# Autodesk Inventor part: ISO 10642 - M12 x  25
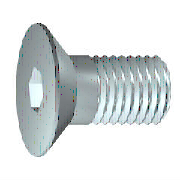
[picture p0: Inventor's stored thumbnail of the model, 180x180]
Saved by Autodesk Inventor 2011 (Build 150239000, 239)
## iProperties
Created: 2010-02
Part Number: ISO 10642 - M12 x  25
Material: Steel
Description: Hexagon Socket Countersunk Head Screw-1 - Product grade A
Document SubType Name: Modeling
Standard: ISO 10642
Designer: 129877
Standard Revision: Second edition 2004-03-01
Standards Organization: ISO
Language: en-US
Size Designation: M12 x  25
Categories: <MemberInstance><Categories><Category DisplayName="Fasteners" InternalName="e4da775c-781d-43d5-af7c-5136215cf5a6" Mnemonic="FSTN"><Category DisplayName="Bolts"
Density: 7.85 g/cm^3
Mass: 29.8359 g
Surface Area: 18.9895 cm^2
Volume: 3.80075 cm^3
IsCustomPart: 0
Author: 129877
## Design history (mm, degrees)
body "Solid1"
workplane "Work Plane1"
revolve "Body" stored, may be unused: angle "d13" = 90 deg
sketch "Sketch2"
  geometry: L1 (0, -16.184)-(0, 16.184) reference; L2 (-16.184, 0)-(16.184, 0) reference; L3 (4.619, 0)-(2.309, -4); L4 (2.309, -4)-(-2.309, -4); L5 (-2.309, -4)-(-4.619, 0); L6 (-4.619, 0)-(-2.309, 4); L7 (-2.309, 4)-(2.309, 4); L8 (2.309, 4)-(4.619, 0); A1 r 4.619 centre (0, 0) between (0, 4.619) and (4.619, 0) reference; 2 further points
  constraints: 12 end point, 2 coincident, 2 point on circle, 2 point on line, 12 other
extrude "Slot" join sketch "Sketch2" taper "d14" = 0 deg; stored distance "d30" = 10
feature "Thread" dims "d15" = 11.5 (= GEL), "d16" = 0
chamfer "Chamfer1" distance "d17" = 1.07354 (= -0.5 x SPD + 0.5 x GD); stored, may be unused: second distance "d18" = 1.07354 (= GUL), angle "d39" = 45 deg
sketch "Sketch1"
  geometry: L1 (25, 0)-(25, 6); L2 (25, 6)-(13.5, 6); L3 (13.5, 6)-(12.426, 6); L4 (0, 11.56)-(0, 4.619); L5 (0, 4.619)-(5.19, 4.619); L6 (5.19, 4.619)-(7.857, 0); L7 (7.857, 0)-(25, 0); L8 (0, 11.56)-(1.88, 11.56); L9 (1.88, 11.56)-(7.44, 6); L10 (12.426, 6)-(7.44, 6); L11 (13.5, 6)-(7.44, 6); L12 (7.44, 6)-(7.44, 6); L13 (-5, 0)-(30, 0) reference; L14 (0, -2.312)-(0, 13.872) reference
  constraints: 24 end point, 4 collinear, 3 parallel
  dimensions: "d0" = 25 distance between parallel lines of L4 L1 (= NLG); "d1" = 11.5 distance from line of L2.end L1 (= GEL); "d2" = 5.19 distance from line of L5.end L4 (= INTI); "d3" = 12 diameter of L2 L7 (= GD); "d6" = 7.44 distance from line of L9.end L4 (= KOH); "d7" = 45 deg angle of L9 L7 (= 0.5 x SEWI); "d8" = 9.2376 diameter of L5 L7 (= 1.1547 x SW); "d9" = 60 deg angle of L6 L7; "d10" = 23.12 diameter of L8 L7 (= KOD); "d11" = 12 diameter of L10 L7 (= BDM); "d12" = 1.07354 distance of L3.end L2.end (= GAL)
other parameters: "NLG" = 25 [user parameter; used in 1 equation term], "INTI" = 5.19 [user parameter; used in 1 equation term], "GEL" = 11.5 [user parameter; used in 2 equation terms], "GAL" = 1.07354 (= 0.61345 x PTC) [user parameter; used in 1 equation term], "KOH" = 7.44 [user parameter; used in 1 equation term], "KOD" = 23.12 [user parameter; used in 1 equation term], "GUL" = 1.07354 (= 0.61345 x PTC) [user parameter; used in 1 equation term], "SPD" = 9.85293 (= NND - 1.2269 x PTC) [user parameter; used in 1 equation term], "BDM" = 12 (= NND) [user parameter; used in 1 equation term], "GD" = 12 (= NND) [user parameter; used in 2 equation terms], "SEWI" = 90 deg [user parameter; used in 1 equation term], "d20" = 0, "SW" = 8 [user parameter; used in 1 equation term], "d43" = 0, "d44" = 0, "TOA" = 30 deg [user parameter], "GD1" = 9.85293 (= THREADDIA - 1.2269 x PTC) [user parameter], "EPV" = 13.44 [user parameter], "THREADDIA" = 12 [user parameter; used in 1 equation term], "TPU" = 5.71429 (computed from PTC) [user parameter], "PTC" = 1.75 [user parameter; used in 5 equation terms], "NND" = 12 [user parameter; used in 3 equation terms], "E0" = 9.24 [user parameter], "THREADDESC" = 12.345 [user parameter]
